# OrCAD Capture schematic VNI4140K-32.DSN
size D
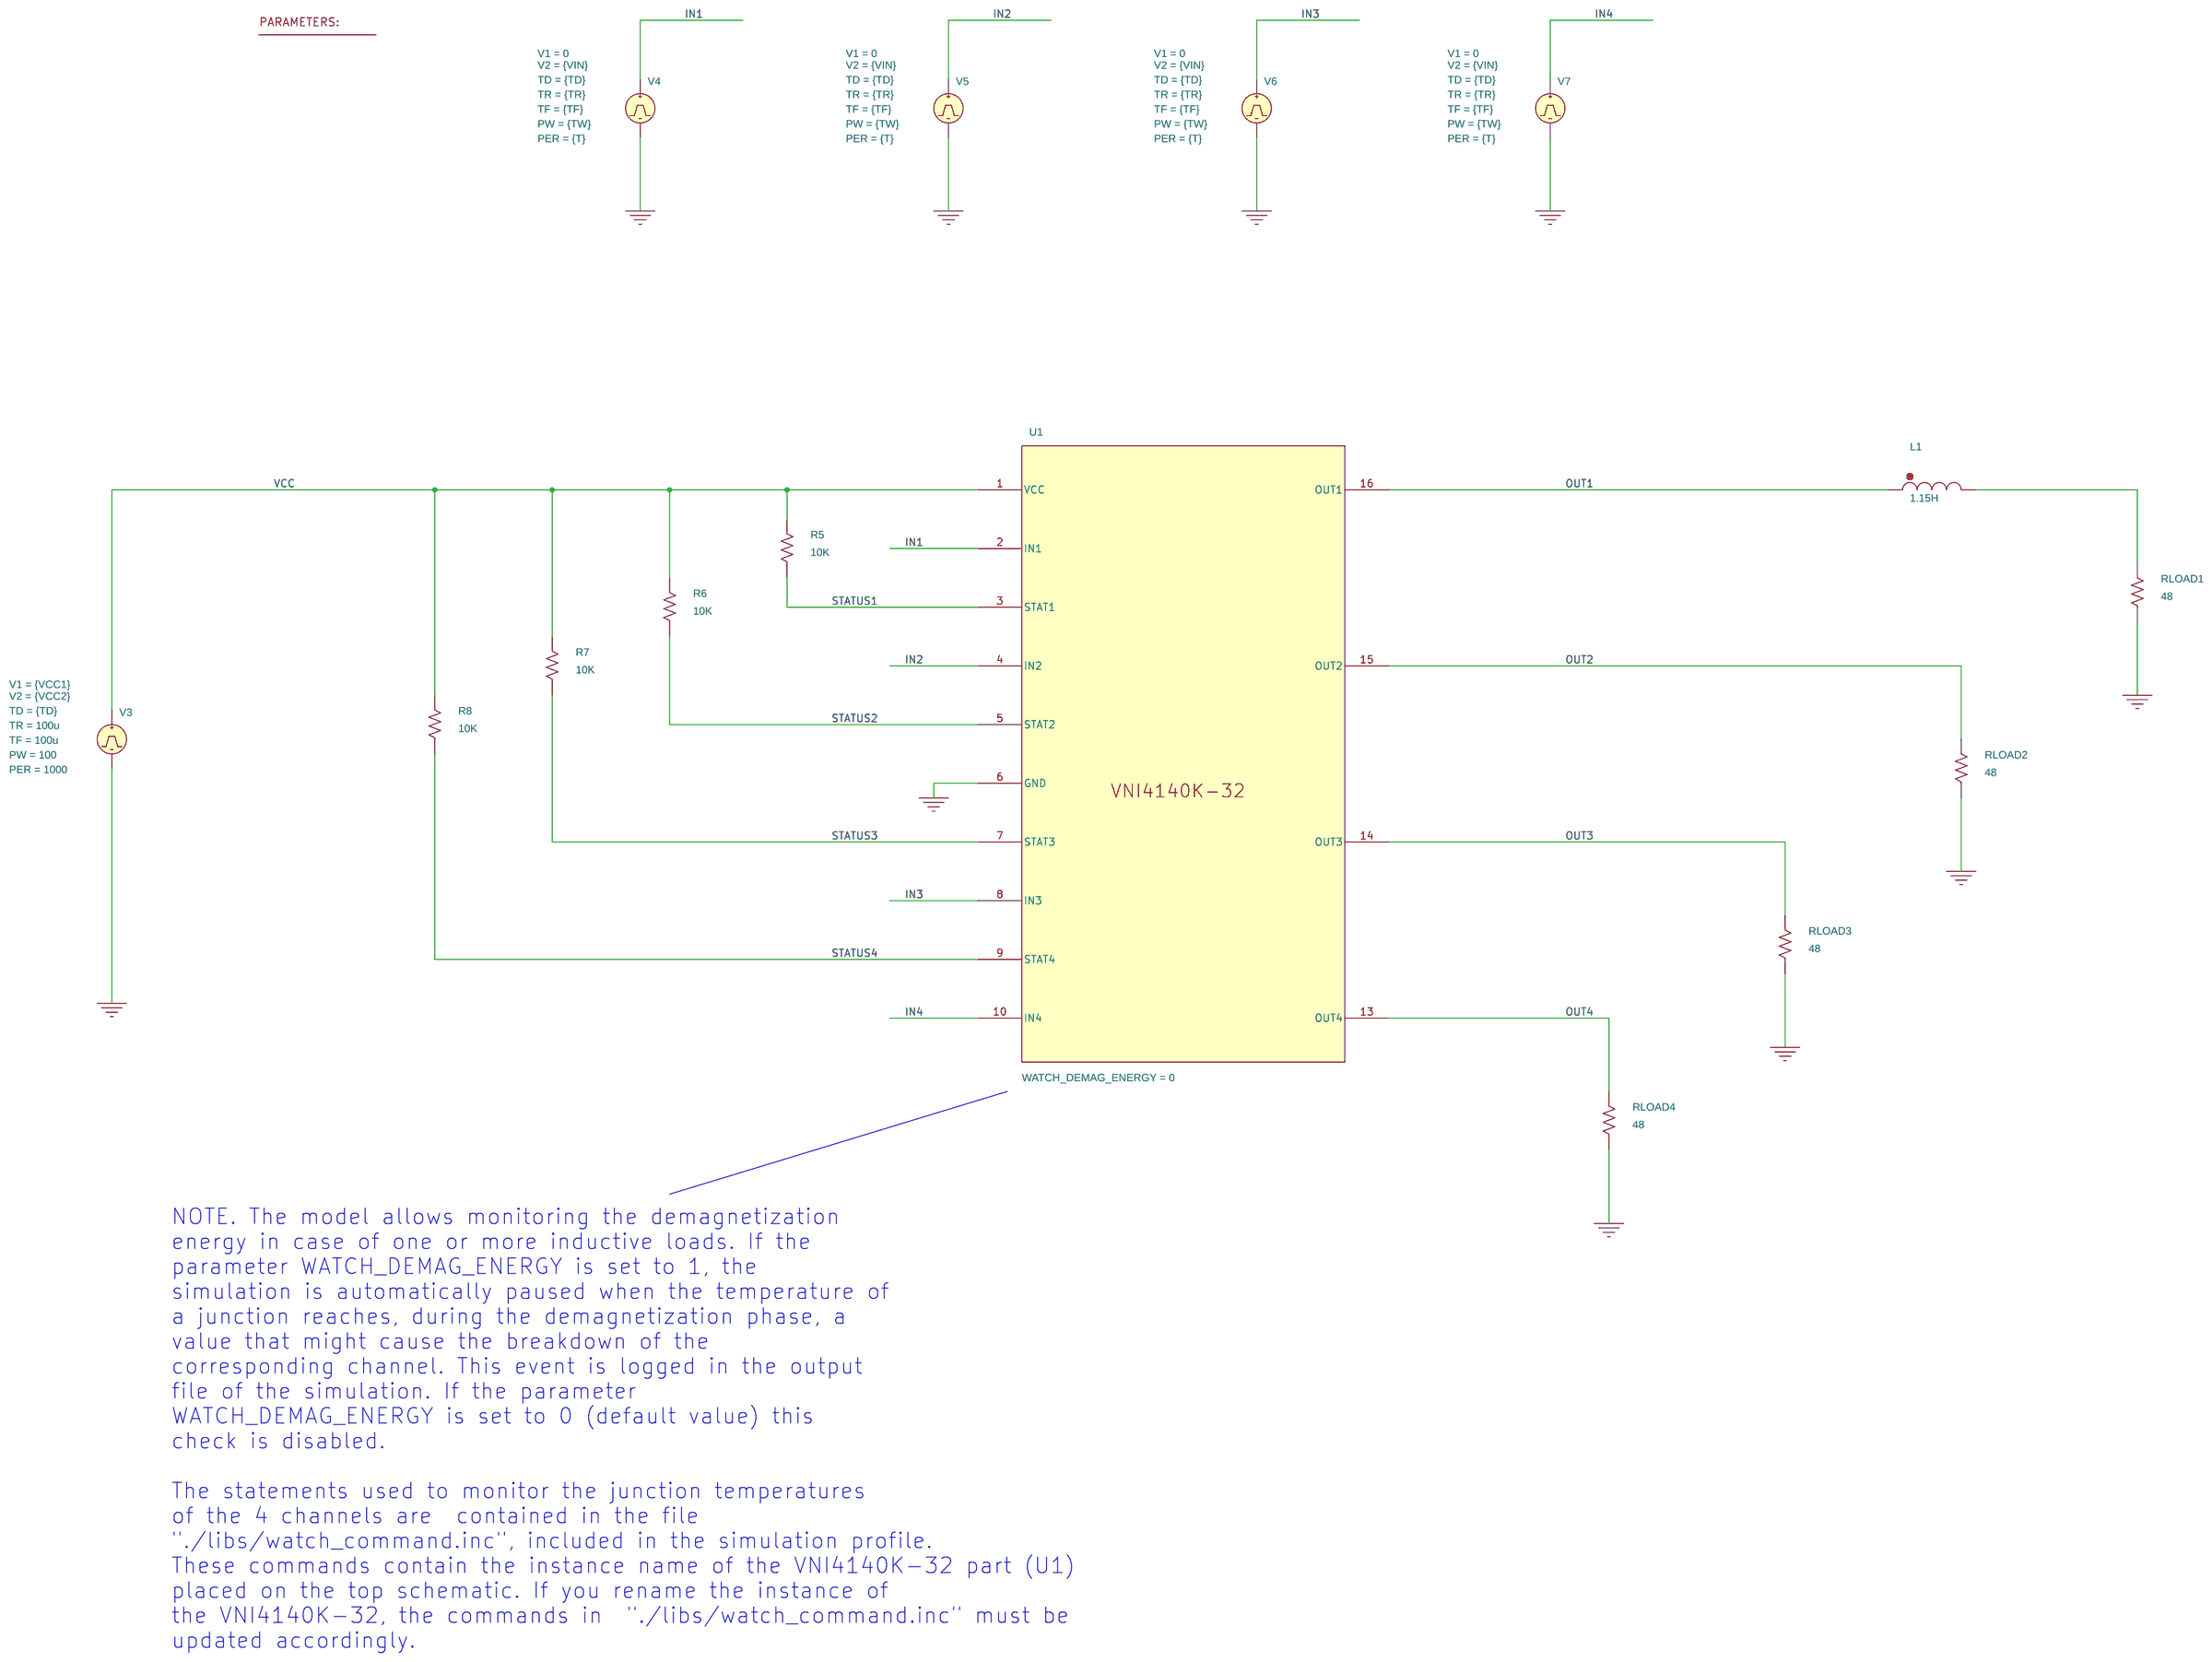
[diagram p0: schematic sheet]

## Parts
1  PARAM
L1  1.15H  [DISC/.350x.175/LS.200x.100/.034]
R5  10K  [AX/RC05]
R6  10K  [AX/RC05]
R7  10K  [AX/RC05]
R8  10K  [AX/RC05]
RLOAD1  48  [AX/RC05]
RLOAD2  48  [AX/RC05]
RLOAD3  48  [AX/RC05]
RLOAD4  48  [AX/RC05]
U1  VNI4140K-32
V3  VPULSE
V4  VPULSE
V5  VPULSE
V6  VPULSE
V7  VPULSE

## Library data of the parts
1 = PARAM: T: {1/3.5}; TD: 10m; TF: 0.1u; TR: 0.1u; TW: {0.8*T}; VCC1: 0; VCC2: 24; VIN: 3.3
L1 = L
R5-R8 RLOAD1-RLOAD4 = R
U1 = VNI4140K-32_0: WATCH_DEMAG_ENERGY: 0
V3 = VPULSE: PER: 1000; PW: 100; TD: {TD}; TF: 100u; TR: 100u; V1: {VCC1}; V2: {VCC2}
V4-V7 = VPULSE: PER: {T}; PW: {TW}; TD: {TD}; TF: {TF}; TR: {TR}; V1: 0; V2: {VIN}

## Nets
VCC: R5.2 R6.2 R7.2 R8.2 U1.1(VCC) V3.1(+)
0: RLOAD1.1 RLOAD2.1 RLOAD3.1 RLOAD4.1 U1.6(GND) V3.2(-) V4.2(-) V5.2(-) V6.2(-) V7.2(-)
IN1: U1.2(IN1) V4.1(+)
IN2: U1.4(IN2) V5.1(+)
IN3: U1.8(IN3) V6.1(+)
IN4: U1.10(IN4) V7.1(+)
OUT1: L1.1 U1.16(OUT1)
OUT2: RLOAD2.2 U1.15(OUT2)
OUT3: RLOAD3.2 U1.14(OUT3)
OUT4: RLOAD4.2 U1.13(OUT4)
STATUS1: R5.1 U1.3(STAT1)
STATUS2: R6.1 U1.5(STAT2)
STATUS3: R7.1 U1.7(STAT3)
STATUS4: R8.1 U1.9(STAT4)
N67382: L1.2 RLOAD1.2

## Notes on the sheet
- NOTE. The model allows monitoring the demagnetization
  energy in case of one or more inductive loads. If the
  parameter WATCH_DEMAG_ENERGY is set to 1, the
  simulation is automatically paused when the temperature of
  a junction reaches, during the demagnetization phase, a
  value that might cause the breakdown of the
  corresponding channel. This event is logged in the output
  file of the simulation. If the parameter
  WATCH_DEMAG_ENERGY is set to 0 (default value) this
  check is disabled.
  The statements used to monitor the junction temperatures
  of the 4 channels are  contained in the file
  "./libs/watch_command.inc", included in the simulation profile.
  These commands contain the instance name of the VNI4140K-32 part (U1)
  placed on the top schematic. If you rename the instance of
  the VNI4140K-32, the commands in  "./libs/watch_command.inc" must be
  updated accordingly.
